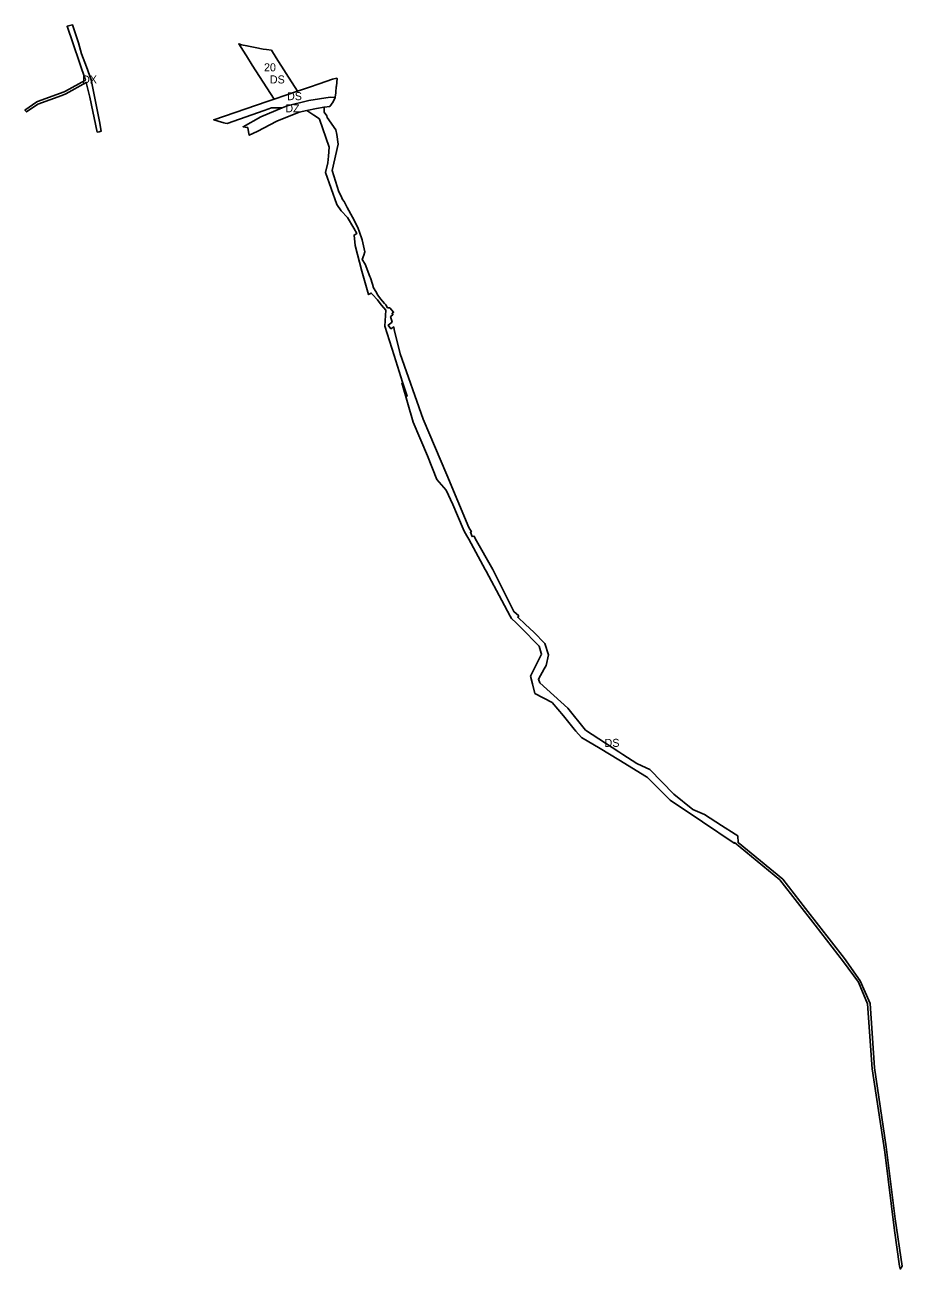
# Model space of a CAD drawing. Extents: x -477403 to -475386, y -1156331 to -1149624.
# Drawn here: x -476484 to -475386, y -1156331 to -1154776 of the extents above; entities that cross this region are included whole.
import ezdxf

# ---------------------------------------------------------------- set-up
doc = ezdxf.new("R2010")
doc.units = 0
for name, color, linetype in [('19', 7, 'Continuous'), ('4', 7, 'Continuous'), ('5', 7, 'Continuous'), ('61', 7, 'Continuous'), ('7', 7, 'Continuous')]:
    doc.layers.add(name, color=color, linetype=linetype)

msp = doc.modelspace()

# ---------------------------------------------------------------- linework, layer by layer
at = {"layer": '19'}
msp.add_lwpolyline([(-476412.7, -1154811.69), (-476406.23, -1154828.01), (-476400.58, -1154844.16), (-476398.48, -1154854.82), (-476396.86, -1154863.05), (-476390.29, -1154896.4), (-476388.207, -1154908.564), (-476390.448, -1154909.183), (-476392.948, -1154909.636), (-476402.22, -1154865.85), (-476406.75, -1154847.63), (-476432.08, -1154861.86), (-476437.477, -1154863.812), (-476467.47, -1154874.66), (-476481.308, -1154884.405), (-476481.806, -1154883.969), (-476483.513, -1154882.184), (-476482.399, -1154881.505), (-476469.851, -1154872.668), (-476467.738, -1154871.567), (-476434.157, -1154859.421), (-476432.57, -1154858.694), (-476407.736, -1154844.743), (-476430.749, -1154777.387), (-476423.76, -1154775.65), (-476416.5, -1154797.89)], close=True, dxfattribs=at)
at = {"layer": '4'}
for points in [[(-476092.998, -1154842.52), (-476093.92, -1154852.23), (-476094, -1154853.04), (-476094.65, -1154859.83), (-476094.697, -1154860.296), (-476094.73, -1154860.63), (-476095.23, -1154865.95), (-476095.348, -1154866.208), (-476101.87, -1154865.88), (-476128.36, -1154870.24), (-476155.34, -1154876.66), (-476161.55, -1154879.52), (-476175.23, -1154879.31), (-476184.16, -1154882.47), (-476230.625, -1154898.752), (-476232.853, -1154898.289), (-476234.762, -1154897.873), (-476241.554, -1154896.069), (-476247.306, -1154894.324), (-476180.31, -1154871.3), (-476171.864, -1154868.439), (-476142.596, -1154858.524), (-476127.44, -1154853.39), (-476115.23, -1154849.25), (-476098.66, -1154843.43), (-476093.41, -1154842.45)], [(-476105.777, -1154889.29), (-476105.62, -1154891.31), (-476094.47, -1154906.84), (-476093.219, -1154912.705), (-476091.85, -1154924.85), (-476099.27, -1154957.48), (-476090.7, -1154984.39), (-476087.849, -1154989.709), (-476086.24, -1154993.76), (-476084.312, -1154996.31), (-476080.234, -1155003.918), (-476073.71, -1155016.09), (-476066.93, -1155028.87), (-476064.94, -1155034.661), (-476061.58, -1155044.44), (-476058.29, -1155059.29), (-476059.523, -1155063.433), (-476061.69, -1155068.87), (-476057.951, -1155074.72), (-476051.866, -1155090.183), (-476051.39, -1155091.89), (-476048.93, -1155099.82), (-476048.875, -1155099.909), (-476047.54, -1155104.47), (-476044.63, -1155109), (-476042.27, -1155113.53), (-476038.8, -1155117.87), (-476033.55, -1155123.72), (-476032.24, -1155125.71), (-476029.96, -1155129.15), (-476027.1, -1155129.49), (-476022.46, -1155134.87), (-476024.2, -1155136), (-476023.15, -1155138.06), (-476024.91, -1155139.21), (-476026.15, -1155140.01), (-476024.26, -1155147.07), (-476029.11, -1155150.97), (-476025.73, -1155155.4), (-476022.1, -1155153.08), (-476021.67, -1155156.19), (-476014.32, -1155186.77), (-475985.43, -1155268.37), (-475955.81, -1155337.85), (-475928.37, -1155404.01), (-475925.1, -1155409.17), (-475926.21, -1155409.75), (-475924.26, -1155415.18), (-475921.62, -1155414.6), (-475920.25, -1155417.55), (-475898.06, -1155456.41), (-475871.8, -1155508.91), (-475865.79, -1155514.39), (-475867.16, -1155515.97), (-475857.22, -1155525.18), (-475847.13, -1155534.53), (-475833.35, -1155548.97), (-475828.6, -1155562.89), (-475831.45, -1155576.49), (-475833.87, -1155580.5), (-475841.2, -1155593.36), (-475839.51, -1155597.89), (-475804.49, -1155629.68), (-475782.13, -1155657.2), (-475757.25, -1155673.44), (-475740.55, -1155684.27), (-475735.68, -1155687.43), (-475718.24, -1155698.74), (-475712.03, -1155701.69), (-475702.01, -1155706.44), (-475671.85, -1155737.22), (-475648.03, -1155756.52), (-475633.37, -1155762.74), (-475612.17, -1155776.27), (-475595.3, -1155787.03), (-475591.73, -1155789.31), (-475591.51, -1155797.63), (-475535.53, -1155843.5), (-475507.17, -1155880.19), (-475458.46, -1155942.5), (-475438.85, -1155970.33), (-475426.41, -1155999.01), (-475420.93, -1156079.14), (-475406.17, -1156178.03), (-475395.1, -1156268.17), (-475386.39, -1156327.1), (-475386.33, -1156327.176), (-475388.708, -1156330.831), (-475388.96, -1156330.51), (-475389.44, -1156327.24), (-475396.04, -1156282.41), (-475408.17, -1156184.46), (-475423.77, -1156080.4), (-475429.47, -1155999.11), (-475441.06, -1155972.02), (-475459.62, -1155946.82), (-475494.94, -1155900.96), (-475539.43, -1155844.34), (-475595.83, -1155797.61), (-475596.36, -1155798.64), (-475636.03, -1155771.59), (-475676.44, -1155744.5), (-475704.91, -1155716.45), (-475706.2, -1155715.64), (-475740.44, -1155694.31), (-475764.01, -1155680.26), (-475787.46, -1155666.27), (-475794.53, -1155658.25), (-475796.71, -1155655.78), (-475810.05, -1155639.12), (-475824.23, -1155622.62), (-475845.68, -1155611.18), (-475848.81, -1155599.1), (-475851.27, -1155589.62), (-475840.97, -1155569.59), (-475837.25, -1155562.36), (-475837.71, -1155560.9), (-475840.41, -1155552.24), (-475850.01, -1155542.6), (-475853.59, -1155538.64), (-475868.96, -1155522.93), (-475874.97, -1155517.56), (-475876.68, -1155514.66), (-475887.17, -1155494.94), (-475906.472, -1155458.422), (-475907.62, -1155456.25), (-475928.32, -1155418.47), (-475930.58, -1155414.33), (-475933.9, -1155408.28), (-475942.52, -1155388.67), (-475948.37, -1155375.28), (-475956.52, -1155357.2), (-475968.3, -1155343.75), (-475979.79, -1155314.44), (-475997.71, -1155272.32), (-476011.95, -1155223.19), (-476005.49, -1155239.75), (-476011.03, -1155222.4), (-476021.78, -1155188.72), (-476033.11, -1155152.03), (-476032.11, -1155132.13), (-476037.37, -1155126.05), (-476041.61, -1155120.41), (-476042.6, -1155119.32), (-476048.54, -1155112.78), (-476050.21, -1155110.86), (-476053.56, -1155112.66), (-476056.1, -1155104.04), (-476061.93, -1155083.39), (-476070.37, -1155051.2), (-476071.73, -1155038.32), (-476068.13, -1155036.38), (-476072.25, -1155029.59), (-476080.17, -1155016.53), (-476088.01, -1155007.91), (-476093.35, -1154999.97), (-476107.45, -1154960.33), (-476104.73, -1154947.91), (-476103.63, -1154939.84), (-476102.98, -1154928.64), (-476114.89, -1154893.34), (-476114.98, -1154893.08), (-476122.02, -1154888.37), (-476130.78, -1154882.52), (-476118.81, -1154880.19), (-476109.24, -1154878.33), (-476109.12, -1154884.59)]]:
    msp.add_lwpolyline(points, close=True, dxfattribs=at)
at = {"layer": '5'}
msp.add_lwpolyline([(-476175.241, -1154807.456), (-476169.201, -1154816.905), (-476156.615, -1154836.593), (-476142.596, -1154858.524), (-476171.864, -1154868.439), (-476199.071, -1154825.876), (-476206.391, -1154814.425), (-476207.294, -1154813.013), (-476216.058, -1154799.303), (-476212.51, -1154800.38), (-476205.877, -1154801.758), (-476195.607, -1154803.892), (-476185.51, -1154805.99), (-476181.145, -1154806.613)], close=True, dxfattribs=at)
at = {"layer": '7'}
msp.add_lwpolyline([(-476095.348, -1154866.208), (-476097.86, -1154871.73), (-476102.266, -1154877.604), (-476109.24, -1154878.33), (-476118.81, -1154880.19), (-476130.78, -1154882.52), (-476140.49, -1154884.87), (-476168.55, -1154896.08), (-476193.18, -1154908.72), (-476202.982, -1154913.681), (-476204.013, -1154909.166), (-476204.699, -1154904.101), (-476205.853, -1154903.899), (-476210.597, -1154902.913), (-476188.49, -1154890.74), (-476161.55, -1154879.52), (-476155.34, -1154876.66), (-476128.36, -1154870.24), (-476101.87, -1154865.88)], close=True, dxfattribs=at)

# ---------------------------------------------------------------- texts
at = {"layer": '19'}
msp.add_text('DX', height=10, dxfattribs=at).set_placement((-476411.948, -1154848.872))
at = {"layer": '4'}
for p in [(-476155.561, -1154869.757), (-475758.47, -1155678.044)]:
    msp.add_text('DS', height=10, dxfattribs=at).set_placement(p)
at = {"layer": '5'}
msp.add_text('DS', height=10, dxfattribs=at).set_placement((-476177.089, -1154848.828))
at = {"layer": '61'}
msp.add_text('20', height=10, dxfattribs=at).set_placement((-476184.411, -1154833.68))
at = {"layer": '7'}
msp.add_text('DZ', height=10, dxfattribs=at).set_placement((-476157.687, -1154884.905))

doc.saveas('drawing.dxf')
